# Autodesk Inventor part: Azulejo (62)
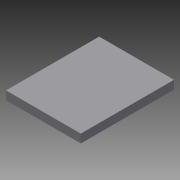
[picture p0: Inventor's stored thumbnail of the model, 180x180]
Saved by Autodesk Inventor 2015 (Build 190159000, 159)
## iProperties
Created: 2015-04
Part Number: Azulejo (62)
Material: Genérico
Document SubType Name: Modeling
Designer: Felipe
Density: 1 g/cm^3
Appearance: Padrão
Author: Felipe
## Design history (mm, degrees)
sketch "Sketch1"
  geometry: L1 (7081.362, 848.164)-(5601.362, 848.164); L2 (5581.362, 848.164)-(4101.362, 848.164); L3 (4081.362, 848.164)-(2601.362, 848.164); L4 (2581.362, 728.164)-(125.504, 728.164); L5 (7101.362, 848.164)-(7101.362, 908.164); L6 (5601.362, 848.164)-(5601.362, 908.164); L7 (5601.362, 908.164)-(7081.362, 908.164); L8 (4101.362, 848.164)-(4101.362, 908.164); L9 (4101.362, 908.164)-(5581.362, 908.164); L10 (5581.362, 908.164)-(5581.362, 848.164); L11 (2601.362, 848.164)-(2601.362, 908.164); L12 (2601.362, 908.164)-(4081.362, 908.164); L13 (4081.362, 908.164)-(4081.362, 848.164); L14 (7081.362, 908.164)-(7081.362, 848.164); L15 (1101.362, 728.164)-(1101.362, 788.164); L16 (1101.362, 788.164)-(2581.362, 788.164); L17 (2581.362, 788.164)-(2581.362, 728.164); L18 (655.504, 728.164)-(655.504, 708.268); L19 (115.504, 828.363)-(115.504, 88.164); L20 (125.504, 828.363)-(125.504, 88.164); L21 (655.504, -31.836)-(655.504, 768.164); L22 (7101.362, 888.164)-(7101.362, 848.164); L23 (5601.362, 168.164)-(5601.362, 908.164); L24 (5601.362, 908.164)-(7081.362, 908.164); L25 (7081.362, 888.164)-(7081.362, 848.164); L26 (5581.362, 908.164)-(5181.362, 908.164); L27 (5581.362, 88.164)-(5581.362, 888.164); L28 (4101.362, 908.164)-(5101.362, 908.164); L29 (4101.362, 88.164)-(4101.362, 888.164); L30 (4081.362, 88.164)-(4081.362, 888.164); L31 (4081.362, 908.164)-(2601.362, 908.164); L32 (2601.362, 888.164)-(2601.362, 88.164); L33 (2581.362, -31.836)-(2581.362, 768.164); L34 (2581.362, 788.164)-(1101.362, 788.164); L35 (1101.362, 768.164)-(1101.362, -31.836); L36 (1081.362, 908.164)-(681.362, 908.164); L37 (155.504, 88.164)-(155.504, 68.164); L38 (155.504, 68.164)-(655.504, 68.164); L39 (1601.362, 88.164)-(1601.362, 68.164); L40 (1601.362, 68.164)-(1101.362, 68.164); L41 (3601.362, 88.164)-(3601.362, 68.164); L42 (3601.362, 68.164)-(2601.362, 68.164); L43 (5161.362, 88.164)-(5161.362, 848.164); L44 (5161.362, 848.164)-(5581.362, 848.164); L45 (5581.362, 848.164)-(5581.362, 88.164); L46 (5581.362, 88.164)-(5161.362, 88.164); L47 (5161.362, 88.164)-(5161.362, 848.164); L48 (655.504, 68.164)-(125.504, 68.164); L49 (125.504, 68.164)-(125.504, 728.164); L50 (655.504, 728.164)-(655.504, 68.164); L51 (5161.362, 88.164)-(4101.362, 88.164); L52 (4101.362, 88.164)-(4101.362, 848.164); L53 (4101.362, 848.164)-(5161.362, 848.164); L54 (5161.362, 848.164)-(5161.362, 88.164); L55 (655.504, 68.164)-(125.504, 68.164); L56 (125.504, 68.164)-(125.504, 728.164); L57 (125.504, 728.164)-(655.504, 728.164); L58 (655.504, 728.164)-(655.504, 68.164); 1 further point
  constraints: 116 end point, 21 point on line, 7 parallel, 4 horizontal, 4 perpendicular
  dimensions: "d2" = 125.50386 distance from line of L20 point (0, 0); "d3" = 68.16406 distance from line of L48 point (0, 0); "d4" = 660 distance between parallel lines of L4 L48; "d5" = 530 distance between parallel lines of L20 L21
extrude "Extrusion1" new body sketch "Sketch1" distance "d0" = 60; taper "d1" = 0 deg
body "Solid1"
